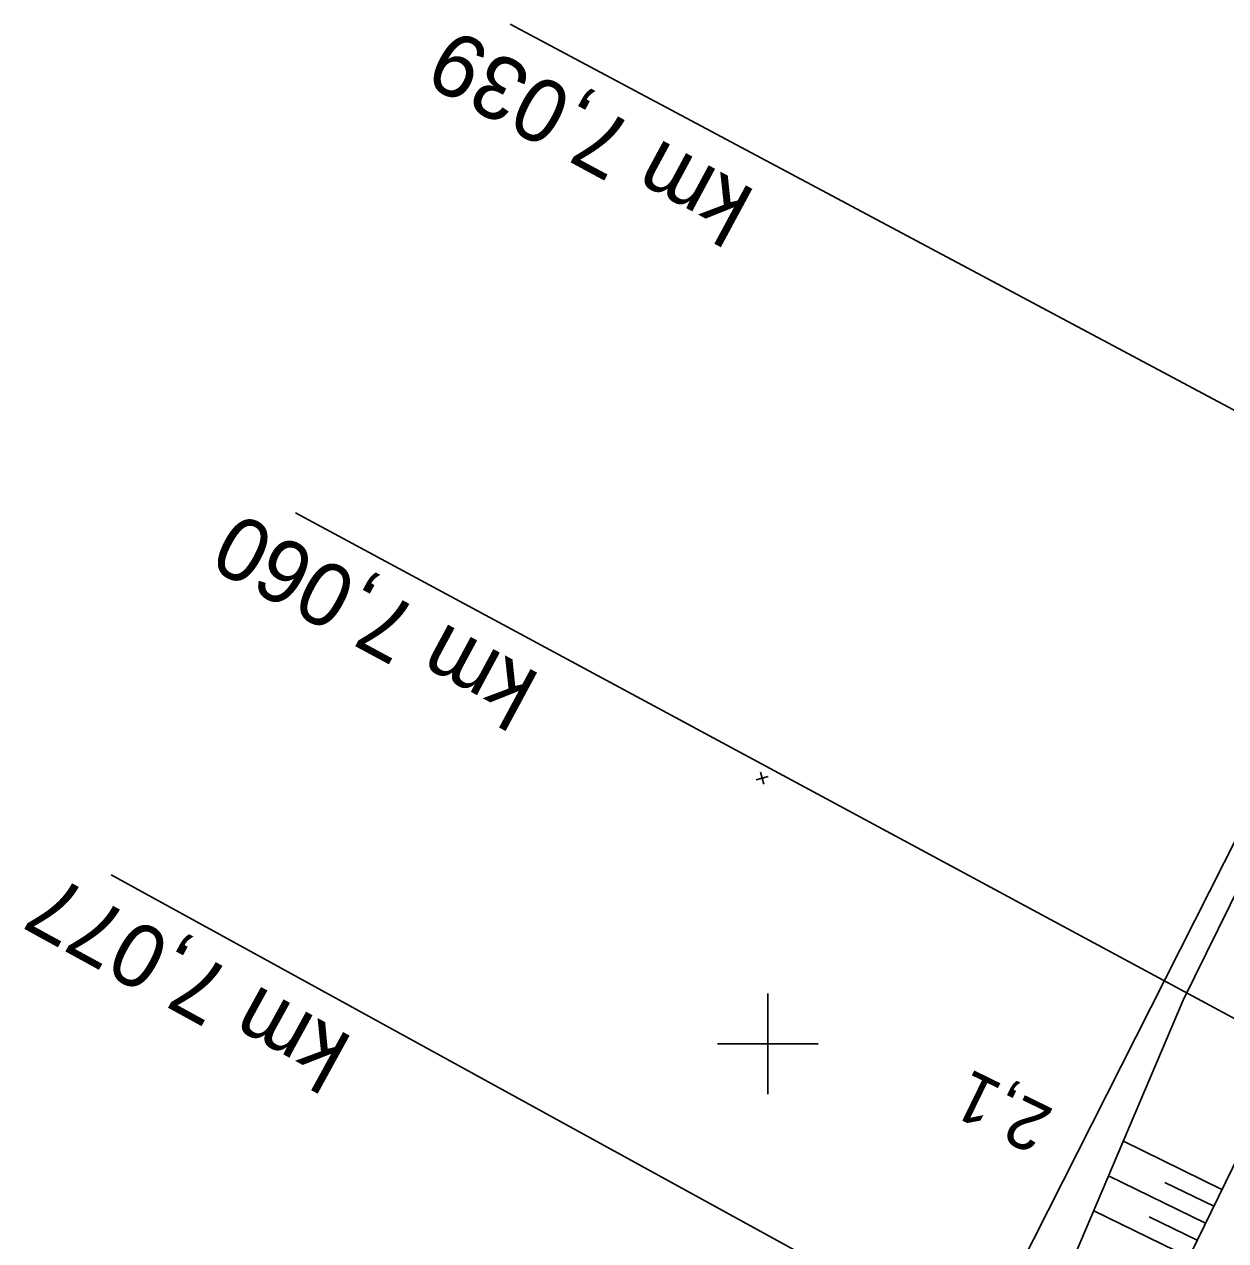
# Model space of a CAD drawing. Extents: x -795094 to -794639, y -1135368 to -1134681.
# Drawn here: x -794929.52 to -794881.82, y -1135007.81 to -1134959.53 of the extents above; entities that cross this region are included whole.
import ezdxf

# ---------------------------------------------------------------- set-up
doc = ezdxf.new("R2010")
doc.units = 0
for name, color, linetype in [('0381KM005-009P - Vrstva 3', 7, 'Continuous'), ('0381KM005-009P - Vrstva 48', 7, 'Continuous'), ('0381KM005-009P - Vrstva 49', 7, 'Continuous'), ('0381KM005-009P - Vrstva 6', 7, 'Continuous'), ('0381KM005-009P - Vrstva 8', 7, 'Continuous'), ('hran DP - hran DP', 7, 'Continuous'), ('krizky_1000 - Vrstva 1', 7, 'Continuous')]:
    doc.layers.add(name, color=color, linetype=linetype)

msp = doc.modelspace()

# ---------------------------------------------------------------- linework, layer by layer
at = {"layer": '0381KM005-009P - Vrstva 3'}
msp.add_line((-794882.938, -1135016.954), (-794926.069, -1134993.289), dxfattribs=at)
at = {"layer": '0381KM005-009P - Vrstva 48'}
for p, q in [((-794881.969, -1135005.772), (-794885.885, -1135003.859)), ((-794882.628, -1135007.12), (-794886.473, -1135005.241)), ((-794882.298, -1135006.446), (-794884.239, -1135005.498)), ((-794883.286, -1135008.468), (-794887.061, -1135006.624)), ((-794882.957, -1135007.794), (-794884.862, -1135006.863))]:
    msp.add_line(p, q, dxfattribs=at)
at = {"layer": '0381KM005-009P - Vrstva 49'}
for p, q in [((-794868.24, -1134967.149), (-794883.505, -1134998.267)), ((-794899.985, -1134989.378), (-794900.465, -1134989.522)), ((-794900.297, -1134989.21), (-794900.153, -1134989.69)), ((-794883.505, -1134998.267), (-794891.468, -1135016.979)), ((-794879, -1134999.695), (-794890.343, -1135022.912))]:
    msp.add_line(p, q, dxfattribs=at)
at = {"layer": '0381KM005-009P - Vrstva 6'}
msp.add_line((-794877.804, -1135000.976), (-794918.759, -1134978.921), dxfattribs=at)
at = {"layer": '0381KM005-009P - Vrstva 8'}
msp.add_line((-794867.871, -1134982.096), (-794910.227, -1134959.525), dxfattribs=at)
at = {"layer": 'hran DP - hran DP'}
msp.add_line((-794899.86, -1135028.32), (-794880.53, -1134990.11), dxfattribs=at)
at = {"layer": 'krizky_1000 - Vrstva 1'}
for points in [[(-794900, -1134998), (-794900, -1135002)], [(-794902, -1135000), (-794898, -1135000)]]:
    msp.add_lwpolyline(points, dxfattribs=at)

# ---------------------------------------------------------------- texts
at = {"layer": '0381KM005-009P - Vrstva 3'}
msp.add_text('km 7,077', height=2.5, rotation=151.2467, dxfattribs=at).set_placement((-794916.408, -1134999.776))
at = {"layer": '0381KM005-009P - Vrstva 48'}
msp.add_text('2,1', height=2, rotation=153.9615, dxfattribs=at).set_placement((-794888.582, -1135002.628))
at = {"layer": '0381KM005-009P - Vrstva 6'}
msp.add_text('km 7,060', height=2.5, rotation=151.6961, dxfattribs=at).set_placement((-794908.965, -1134985.366))
at = {"layer": '0381KM005-009P - Vrstva 8'}
msp.add_text('km 7,039', height=2.5, rotation=151.6652, dxfattribs=at).set_placement((-794900.417, -1134966.163))

doc.saveas('drawing.dxf')
